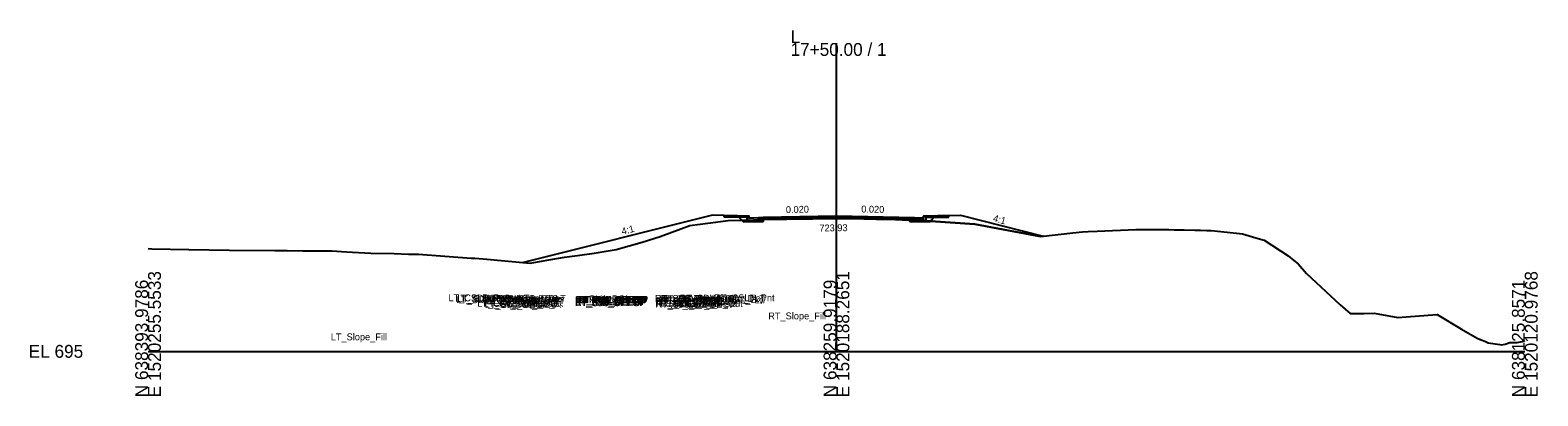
# Model space of a CAD drawing. Extents: x -26 to 3903, y -10 to 9531.
# Drawn here: x -25.7 to 302.8, y 7490.3 to 7570 of the extents above; entities that cross this region are included whole.
import ezdxf

# ---------------------------------------------------------------- set-up
doc = ezdxf.new("R2010")
doc.units = 0
for name, color, linetype in [('Default', 7, 'Continuous'), ('Exist Cross Section Cell', 7, 'Continuous'), ('Exist XS Center Line Elevation Label', 7, 'Continuous'), ('Exist XS Ground Line', 7, 'Continuous'), ('Old_Level_63', 7, 'Continuous'), ('Prop CMT Conc Surface', 7, 'Continuous'), ('Prop CMT Pvmt Course 1', 7, 'Continuous'), ('Prop CMT Pvmt Course 1 CG', 7, 'Continuous'), ('Prop CMT Pvmt Course 2', 7, 'Continuous'), ('Prop CMT Pvmt Course 3', 7, 'Continuous'), ('Prop CMT Pvmt Surface', 7, 'Continuous'), ('Prop CMT Slope Grass', 7, 'Continuous'), ('Prop CMT Subgrade Earthwork', 7, 'Continuous'), ('Prop XS Earthwork Shape', 7, 'Continuous'), ('Prop XS SE Text', 7, 'Continuous'), ('Prop XS Side Slope Text', 7, 'Continuous')]:
    doc.layers.add(name, color=color, linetype=linetype)

msp = doc.modelspace()

# ---------------------------------------------------------------- linework, layer by layer
at = {"layer": 'Exist Cross Section Cell'}
for p, q in [((150, 7500), (150, 7567.16)), ((0, 7500), (150, 7500)), ((150, 7500), (300, 7500))]:
    msp.add_line(p, q, dxfattribs=at)
at = {"layer": 'Exist XS Ground Line'}
msp.add_lwpolyline([(0, 7522.39), (0.84, 7522.36), (8.85, 7522.16), (17.76, 7522.07), (27.59, 7521.96), (30.32, 7521.96), (33.7, 7521.93), (40.08, 7521.87), (43.21, 7521.68), (48.53, 7521.35), (53.65, 7521.28), (56.76, 7521.14), (58.7, 7521.16), (58.9, 7521.15), (70.41, 7520.33), (71.23, 7520.27), (73.04, 7520.12), (83.25, 7519.21), (87.3, 7519.96), (90.72, 7520.54), (93.56, 7520.88), (97.2, 7521.39), (102.03, 7522.19), (107.65, 7523.77), (111.59, 7524.99), (118.07, 7527.43), (120.34, 7527.7), (126.41, 7528.49), (131.93, 7528.67), (132.16, 7528.67), (132.35, 7528.67), (133.42, 7528.71), (133.44, 7528.71), (133.48, 7528.71), (136.39, 7528.76), (136.48, 7528.76), (138.29, 7528.81), (139.2, 7528.82), (140.15, 7528.84), (142.01, 7528.86), (142.06, 7528.86), (144.8, 7528.9), (147.57, 7528.93), (147.59, 7528.93), (147.6, 7528.93), (147.63, 7528.93), (147.71, 7528.93), (149.59, 7528.94), (149.66, 7528.94), (149.83, 7528.94), (150.09, 7528.94), (150.37, 7528.93), (151.3, 7528.92), (153.17, 7528.91), (153.18, 7528.91), (153.18, 7528.91), (153.19, 7528.91), (155.96, 7528.87), (156.89, 7528.85), (158.74, 7528.82), (158.75, 7528.82), (158.76, 7528.82), (160.94, 7528.78), (161.11, 7528.77), (161.35, 7528.77), (164.31, 7528.68), (164.36, 7528.67), (164.39, 7528.67), (166.9, 7528.59), (167.46, 7528.58), (167.89, 7528.56), (170.51, 7528.39), (180.15, 7527.71), (186.33, 7526.54), (194.45, 7525.05), (201.51, 7525.78), (203.6, 7526.01), (204.85, 7526.07), (206.83, 7526.16), (215.21, 7526.54), (216.02, 7526.56), (216.27, 7526.57), (216.96, 7526.57), (219.11, 7526.56), (219.67, 7526.55), (220.21, 7526.55), (221.71, 7526.52), (222.46, 7526.52), (223.56, 7526.5), (225.27, 7526.48), (225.44, 7526.47), (225.77, 7526.47), (228.07, 7526.42), (229.29, 7526.4), (229.3, 7526.4), (229.31, 7526.4), (230.7, 7526.34), (230.74, 7526.34), (231.31, 7526.32), (231.65, 7526.3), (235.13, 7525.94), (238.46, 7525.63), (241.36, 7524.72), (243.19, 7524.22), (248.43, 7520.79), (249.64, 7519.76), (250.59, 7519.04), (252.44, 7516.95), (259.75, 7510.16), (261.94, 7508.23), (264.94, 7508.26), (267.17, 7508.28), (267.98, 7508.14), (272.33, 7507.4), (274.12, 7507.51), (280.91, 7508.04), (286.17, 7504.86), (289.64, 7502.84), (290.49, 7502.49), (291.29, 7502.22), (291.73, 7501.99), (292.04, 7501.84), (294.54, 7501.46), (294.92, 7501.45), (295.75, 7501.57), (296.77, 7501.91), (298.16, 7501.93), (298.34, 7501.93), (299.4, 7502.13), (299.48, 7502.14), (299.56, 7502.2), (300, 7502.34)], dxfattribs=at)
at = {"layer": 'Old_Level_63'}
for p, q in [((131, 7528.98), (131, 7529.48)), ((133, 7529.1), (131, 7528.98)), ((169, 7528.98), (167, 7529.1)), ((169.5, 7529.48), (169, 7529.48)), ((169, 7529.48), (169, 7528.98))]:
    msp.add_line(p, q, dxfattribs=at)
for points in [[(125.5, 7529.25), (125.5, 7529.58)], [(125.5, 7529.58), (130.5, 7529.48)], [(130.5, 7529.15), (125.5, 7529.25)], [(130.5, 7529.49), (130.5, 7529.16)], [(133, 7529.1), (131, 7528.98), (131, 7529.48), (130.5, 7529.48)], [(130.5, 7529.48), (130.5, 7528.47), (133, 7528.52)], [(133, 7528.52), (133, 7529.1)], [(167, 7529.1), (169, 7528.98), (169, 7529.48), (169.5, 7529.48)], [(169.5, 7529.48), (169.5, 7528.47), (167, 7528.52)], [(167, 7528.52), (167, 7529.1)], [(174.5, 7529.58), (169.5, 7529.48)], [(174.5, 7529.58), (169.5, 7529.48)], [(169.5, 7529.48), (169.5, 7529.16)], [(174.5, 7529.26), (169.5, 7529.16)], [(169.5, 7529.16), (174.5, 7529.26)], [(174.5, 7529.26), (174.5, 7529.58)]]:
    msp.add_lwpolyline(points, dxfattribs=at)
at = {"layer": 'Prop CMT Conc Surface'}
for points in [[(130.5, 7529.48), (125.5, 7529.58)], [(131, 7528.97), (131, 7529.47), (130.5, 7529.47)], [(133, 7529.09), (131, 7528.97)], [(167, 7529.09), (169, 7528.97)], [(169, 7528.97), (169, 7529.47), (169.5, 7529.47)], [(169.5, 7529.48), (174.5, 7529.58)], [(80.5, 7511.48), (75.5, 7511.58)], [(81, 7510.97), (81, 7511.47), (80.5, 7511.47)], [(83, 7511.09), (81, 7510.97)], [(117, 7511.09), (119, 7510.97)], [(119, 7510.97), (119, 7511.47), (119.5, 7511.47)], [(119.5, 7511.48), (124.5, 7511.58)]]:
    msp.add_lwpolyline(points, dxfattribs=at)
at = {"layer": 'Prop CMT Pvmt Course 1'}
for points in [[(150, 7529.44), (133, 7529.1)], [(133, 7528.85), (150, 7529.19)], [(133, 7529.1), (133, 7528.85)], [(150, 7529.19), (150, 7529.44)], [(150, 7529.44), (167, 7529.1)], [(150, 7529.19), (150, 7529.44)], [(167, 7528.85), (150, 7529.19)], [(167, 7529.1), (167, 7528.85)]]:
    msp.add_lwpolyline(points, dxfattribs=at)
msp.add_lwpolyline([(150, 7529.19), (150, 7529.31), (150, 7529.31), (150, 7529.19)], close=True, dxfattribs=at)
msp.add_lwpolyline([(150, 7529.19), (150, 7529.31), (150, 7529.31), (150, 7529.19)], close=True, dxfattribs=at)
at = {"layer": 'Prop CMT Pvmt Course 1 CG'}
for points in [[(133, 7528.52), (130, 7528.46), (129.74, 7528.2)], [(129.74, 7528.2), (133, 7528.27)], [(133, 7528.27), (133, 7528.52)], [(167, 7528.52), (170, 7528.46), (170.26, 7528.2)], [(167, 7528.27), (167, 7528.52)], [(170.26, 7528.2), (167, 7528.27)]]:
    msp.add_lwpolyline(points, dxfattribs=at)
at = {"layer": 'Prop CMT Pvmt Course 2'}
for points in [[(134, 7528.87), (133, 7528.85)], [(133, 7528.85), (133, 7528.52)], [(133, 7528.52), (134, 7528.54)], [(166, 7528.87), (167, 7528.85)], [(167, 7528.52), (166, 7528.54)], [(167, 7528.85), (167, 7528.52)]]:
    msp.add_lwpolyline(points, dxfattribs=at)
at = {"layer": 'Prop CMT Pvmt Course 3'}
for points in [[(134, 7528.54), (133, 7528.52)], [(133, 7528.52), (133, 7528.27)], [(133, 7528.27), (134, 7528.29)], [(166, 7528.54), (167, 7528.52)], [(167, 7528.27), (166, 7528.29)], [(167, 7528.52), (167, 7528.27)]]:
    msp.add_lwpolyline(points, dxfattribs=at)
at = {"layer": 'Prop CMT Pvmt Surface'}
for p, q in [((150, 7529.44), (133, 7529.1)), ((167, 7529.1), (150, 7529.44))]:
    msp.add_line(p, q, dxfattribs=at)
for points in [[(134, 7529.12), (133, 7529.1)], [(150, 7529.44), (167, 7529.1)]]:
    msp.add_lwpolyline(points, dxfattribs=at)
at = {"layer": 'Prop CMT Slope Grass'}
for p, q in [((123, 7529.63), (81.83, 7519.34)), ((177, 7529.63), (195.06, 7525.11))]:
    msp.add_line(p, q, dxfattribs=at)
for points in [[(125.5, 7529.58), (123, 7529.63)], [(174.5, 7529.58), (177, 7529.63), (177, 7529.63)]]:
    msp.add_lwpolyline(points, dxfattribs=at)
at = {"layer": 'Prop CMT Subgrade Earthwork'}
for p, q in [((134, 7528.72), (134, 7528.29)), ((166, 7528.62), (166, 7528.29))]:
    msp.add_line(p, q, dxfattribs=at)
for points in [[(133, 7528.27), (129.74, 7528.2), (128.43, 7529.52)], [(134, 7528.29), (133, 7528.27)], [(166, 7528.29), (167, 7528.27)], [(167, 7528.27), (170.26, 7528.2), (171.57, 7529.52)]]:
    msp.add_lwpolyline(points, dxfattribs=at)
at = {"layer": 'Prop XS Earthwork Shape'}
for points in [[(125.5, 7529.58), (123, 7529.63), (81.83, 7519.34), (83.25, 7519.21), (87.3, 7519.96), (90.72, 7520.54), (93.56, 7520.88), (97.2, 7521.39), (102.03, 7522.19), (107.65, 7523.77), (111.59, 7524.99), (118.07, 7527.43), (120.34, 7527.7), (126.41, 7528.49), (129.36, 7528.59), (128.43, 7529.52)], [(125.5, 7529.58), (123, 7529.63), (81.83, 7519.34), (83.25, 7519.21), (87.3, 7519.96), (90.72, 7520.54), (93.56, 7520.88), (97.2, 7521.39), (102.03, 7522.19), (107.65, 7523.77), (111.59, 7524.99), (118.07, 7527.43), (120.34, 7527.7), (126.41, 7528.49), (129.36, 7528.59), (128.43, 7529.52)], [(125.5, 7529.58), (123, 7529.63), (81.83, 7519.34), (83.25, 7519.21), (87.3, 7519.96), (90.72, 7520.54), (93.56, 7520.88), (97.2, 7521.39), (102.03, 7522.19), (107.65, 7523.77), (111.59, 7524.99), (118.07, 7527.43), (120.34, 7527.7), (126.41, 7528.49), (129.36, 7528.59), (128.43, 7529.52)], [(125.5, 7529.58), (123, 7529.63), (81.83, 7519.34), (83.25, 7519.21), (87.3, 7519.96), (90.72, 7520.54), (93.56, 7520.88), (97.2, 7521.39), (102.03, 7522.19), (107.65, 7523.77), (111.59, 7524.99), (118.07, 7527.43), (120.34, 7527.7), (126.41, 7528.49), (129.36, 7528.59), (128.43, 7529.52)], [(130.5, 7529.47), (128.43, 7529.52), (129.36, 7528.59), (131.93, 7528.67), (132.16, 7528.67), (132.35, 7528.67), (133.42, 7528.71), (134, 7528.72), (136.39, 7528.76), (138.29, 7528.81), (139.2, 7528.82), (140.15, 7528.84), (142.01, 7528.86), (144.8, 7528.9), (147.57, 7528.93), (147.71, 7528.93), (149.59, 7528.94), (149.83, 7528.94), (150.09, 7528.94), (150.37, 7528.93), (151.3, 7528.92), (153.17, 7528.91), (155.96, 7528.87), (156.89, 7528.85), (158.74, 7528.82), (160.94, 7528.78), (161.11, 7528.77), (161.35, 7528.77), (164.31, 7528.68), (166, 7528.62), (166.9, 7528.59), (167.46, 7528.58), (167.89, 7528.56), (170.51, 7528.39), (171.57, 7529.52), (169.5, 7529.47), (169, 7529.47), (169, 7528.97), (167, 7529.1), (150, 7529.44), (134, 7529.12), (133, 7529.1), (131, 7528.97), (131, 7529.47)], [(166, 7528.62), (166.9, 7528.59), (167.46, 7528.58), (167.89, 7528.56), (170.51, 7528.39), (171.57, 7529.52), (169.5, 7529.47), (169, 7529.47), (169, 7528.97), (167, 7529.1), (150, 7529.44), (134, 7529.12), (133, 7529.1), (131, 7528.97), (131, 7529.47), (130.5, 7529.47), (128.43, 7529.52), (129.36, 7528.59), (131.93, 7528.67), (132.16, 7528.67), (132.35, 7528.67), (133.42, 7528.71), (134, 7528.72), (136.39, 7528.76), (138.29, 7528.81), (139.2, 7528.82), (140.15, 7528.84), (142.01, 7528.86), (144.8, 7528.9), (147.57, 7528.93), (147.71, 7528.93), (149.59, 7528.94), (149.83, 7528.94), (150.09, 7528.94), (150.37, 7528.93), (151.3, 7528.92), (153.17, 7528.91), (155.96, 7528.87), (156.89, 7528.85), (158.74, 7528.82), (160.94, 7528.78), (161.11, 7528.77), (161.35, 7528.77), (164.31, 7528.68)], [(170.51, 7528.39), (171.57, 7529.52), (169.5, 7529.47), (169, 7529.47), (169, 7528.97), (167, 7529.1), (150, 7529.44), (134, 7529.12), (133, 7529.1), (131, 7528.97), (131, 7529.47), (130.5, 7529.47), (128.43, 7529.52), (129.36, 7528.59), (131.93, 7528.67), (132.16, 7528.67), (132.35, 7528.67), (133.42, 7528.71), (134, 7528.72), (136.39, 7528.76), (138.29, 7528.81), (139.2, 7528.82), (140.15, 7528.84), (142.01, 7528.86), (144.8, 7528.9), (147.57, 7528.93), (147.71, 7528.93), (149.59, 7528.94), (149.83, 7528.94), (150.09, 7528.94), (150.37, 7528.93), (151.3, 7528.92), (153.17, 7528.91), (155.96, 7528.87), (156.89, 7528.85), (158.74, 7528.82), (160.94, 7528.78), (161.11, 7528.77), (161.35, 7528.77), (164.31, 7528.68), (166, 7528.62), (166.9, 7528.59), (167.46, 7528.58), (167.89, 7528.56)], [(167, 7529.1), (150, 7529.44), (134, 7529.12), (133, 7529.1), (131, 7528.97), (131, 7529.47), (130.5, 7529.47), (128.43, 7529.52), (129.36, 7528.59), (131.93, 7528.67), (132.16, 7528.67), (132.35, 7528.67), (133.42, 7528.71), (134, 7528.72), (136.39, 7528.76), (138.29, 7528.81), (139.2, 7528.82), (140.15, 7528.84), (142.01, 7528.86), (144.8, 7528.9), (147.57, 7528.93), (147.71, 7528.93), (149.59, 7528.94), (149.83, 7528.94), (150.09, 7528.94), (150.37, 7528.93), (151.3, 7528.92), (153.17, 7528.91), (155.96, 7528.87), (156.89, 7528.85), (158.74, 7528.82), (160.94, 7528.78), (161.11, 7528.77), (161.35, 7528.77), (164.31, 7528.68), (166, 7528.62), (166.9, 7528.59), (167.46, 7528.58), (167.89, 7528.56), (170.51, 7528.39), (171.57, 7529.52), (169.5, 7529.47), (169, 7529.47), (169, 7528.97)], [(129.74, 7528.2), (129.36, 7528.59), (131.93, 7528.67), (132.16, 7528.67), (132.35, 7528.67), (133.42, 7528.71), (134, 7528.72), (134, 7528.29), (133, 7528.27)], [(133, 7528.27), (129.74, 7528.2), (129.36, 7528.59), (131.93, 7528.67), (132.16, 7528.67), (132.35, 7528.67), (133.42, 7528.71), (134, 7528.72), (134, 7528.29)], [(131.93, 7528.67), (132.16, 7528.67), (132.35, 7528.67), (133.42, 7528.71), (134, 7528.72), (134, 7528.29), (133, 7528.27), (129.74, 7528.2), (129.36, 7528.59)], [(134, 7528.29), (133, 7528.27), (129.74, 7528.2), (129.36, 7528.59), (131.93, 7528.67), (132.16, 7528.67), (132.35, 7528.67), (133.42, 7528.71), (134, 7528.72)], [(170.26, 7528.2), (170.51, 7528.39), (167.89, 7528.56), (167.46, 7528.58), (166.9, 7528.59), (166, 7528.62), (166, 7528.29), (167, 7528.27)], [(166, 7528.62), (166.9, 7528.59), (167.46, 7528.58), (167.89, 7528.56), (170.51, 7528.39), (170.26, 7528.2), (167, 7528.27), (166, 7528.29)], [(166, 7528.29), (167, 7528.27), (170.26, 7528.2), (170.51, 7528.39), (167.89, 7528.56), (167.46, 7528.58), (166.9, 7528.59), (166, 7528.62)], [(166, 7528.29), (167, 7528.27), (170.26, 7528.2), (170.51, 7528.39), (167.89, 7528.56), (167.46, 7528.58), (166.9, 7528.59), (166, 7528.62)], [(177, 7529.63), (195.06, 7525.11), (194.45, 7525.05), (186.33, 7526.54), (180.15, 7527.71), (170.51, 7528.39), (171.57, 7529.52), (174.5, 7529.58)], [(170.51, 7528.39), (171.57, 7529.52), (174.5, 7529.58), (177, 7529.63), (195.06, 7525.11), (194.45, 7525.05), (186.33, 7526.54), (180.15, 7527.71)], [(170.51, 7528.39), (171.57, 7529.52), (174.5, 7529.58), (177, 7529.63), (195.06, 7525.11), (194.45, 7525.05), (186.33, 7526.54), (180.15, 7527.71)], [(170.51, 7528.39), (171.57, 7529.52), (174.5, 7529.58), (177, 7529.63), (195.06, 7525.11), (194.45, 7525.05), (186.33, 7526.54), (180.15, 7527.71)]]:
    msp.add_lwpolyline(points, close=True, dxfattribs=at)

# ---------------------------------------------------------------- texts
at = {"layer": 'Default'}
msp.add_text('-', height=0.0001, dxfattribs=at).set_placement((0, 7500))
at = {"layer": 'Exist Cross Section Cell'}
for s, p in [('L', (140, 7567.16)), ('17+50.00 / 1', (140, 7564.36)), ('EL 695', (-26, 7498.6))]:
    msp.add_text(s, height=2.8, dxfattribs=at).set_placement(p)
for s, p in [('E 1520255.5533', (2.8, 7490)), ('E 1520188.2651', (152.8, 7490)), ('E 1520120.9768', (302.8, 7490)), ('N 638393.9786', (0, 7490)), ('N 638259.9179', (150, 7490)), ('N 638125.8571', (300, 7490))]:
    msp.add_text(s, height=2.8, rotation=90, dxfattribs=at).set_placement(p)
at = {"layer": 'Exist XS Center Line Elevation Label'}
msp.add_text('723.93', height=1.5, rotation=0.8401, dxfattribs=at).set_placement((146.3, 7526.1))
at = {"layer": 'Prop CMT Conc Surface'}
for s, p in [('LT_CSLP_Pnt', (65.45, 7510.91)), ('LT_SDWK_Out_Top', (66.94, 7510.83)), ('LT_SDWK_Out_Bot', (67.12, 7510.5)), ('LT_Sub_Trench_Out_DLT', (67.4, 7510.76)), ('LT_CG1_Shelf_Out', (71.73, 7509.7)), ('LT_SDWK_In_Top', (72.8, 7510.73)), ('LT_CG_Top_BOC', (72.86, 7510.72)), ('LT_SDWK_In_Bot', (72.99, 7510.4)), ('LT_CG_Bot_BOC', (73.07, 7509.71)), ('LT_CG_Top_Face', (73.38, 7510.72)), ('LT_Sub_OEOP', (73.39, 7509.44)), ('LT_CG_Top_Gut', (73.78, 7510.22)), ('LT_PV2_OEOT', (76.62, 7510.09)), ('LT_PV3_OEOT', (76.62, 7509.76)), ('LT_Sub_OEOT', (76.65, 7509.51)), ('LT_PV1_OEOT', (76.8, 7510.34)), ('LT_CG_Bot_IE', (76.88, 7509.76)), ('RT_PV2_OEEOP', (93, 7510.43)), ('RT_PV3_OEEOP', (93, 7510.1)), ('RT_Sub_OEEOP', (93.04, 7509.85)), ('LT_PV2_OEEOP', (93.09, 7510.43)), ('LT_PV3_OEEOP', (93.09, 7510.1)), ('LT_Sub_OEEOP', (93.12, 7509.85)), ('RT_PV1_OEEOP', (93.18, 7510.56)), ('LT_PV1_OEEOP', (93.27, 7510.56)), ('RT_PV2_IEEOP', (93.57, 7510.43)), ('LT_PV2_IEEOP', (93.66, 7510.43)), ('RT_PV1_IEEOP', (93.75, 7510.56)), ('LT_PV1_IEEOP', (93.84, 7510.56)), ('PV2_PGL', (96.03, 7510.43)), ('PV1_PGL', (96.2, 7510.68)), ('RT_Sub_Trench_Out_DLT', (110.46, 7510.76)), ('RT_PV2_OEOT', (110.53, 7510.09)), ('RT_PV3_OEOT', (110.53, 7509.76)), ('RT_Sub_OEOT', (110.56, 7509.51)), ('RT_PV1_OEOT', (110.71, 7510.34)), ('RT_CG_Bot_IE', (110.79, 7509.76)), ('RT_CG_Top_Face', (111.29, 7510.72)), ('RT_CG1_Shelf_Out', (111.64, 7509.7)), ('RT_CG_Top_Gut', (111.69, 7510.22)), ('RT_SDWK_In_Top', (111.71, 7510.73)), ('RT_CG_Top_BOC', (111.77, 7510.72)), ('RT_SDWK_In_Bot', (111.9, 7510.4)), ('RT_CG_Bot_BOC', (111.98, 7509.71)), ('RT_Sub_OEOP', (113.81, 7509.44)), ('RT_SDWK_Out_Top', (115.85, 7510.83)), ('RT_SDWK_Out_Bot', (116.03, 7510.5)), ('RT_CSLP_Pnt', (123.36, 7510.91)), ('RT_Slope_Fill', (135.14, 7506.96)), ('LT_Slope_Fill', (39.81, 7502.4))]:
    msp.add_text(s, height=1.5, dxfattribs=at).set_placement(p)
at = {"layer": 'Prop XS SE Text'}
for rotation, p in [(1.1458, (139, 7530.12)), (358.8542, (155.4, 7530.25))]:
    msp.add_text('0.020', height=1.5, rotation=rotation, dxfattribs=at).set_placement(p)
at = {"layer": 'Prop XS Side Slope Text'}
for rotation, p in [(14.0362, (103.36, 7525.38)), (344.7445, (184, 7528.36))]:
    msp.add_text('4:1', height=1.5, rotation=rotation, dxfattribs=at).set_placement(p)

doc.saveas('drawing.dxf')
